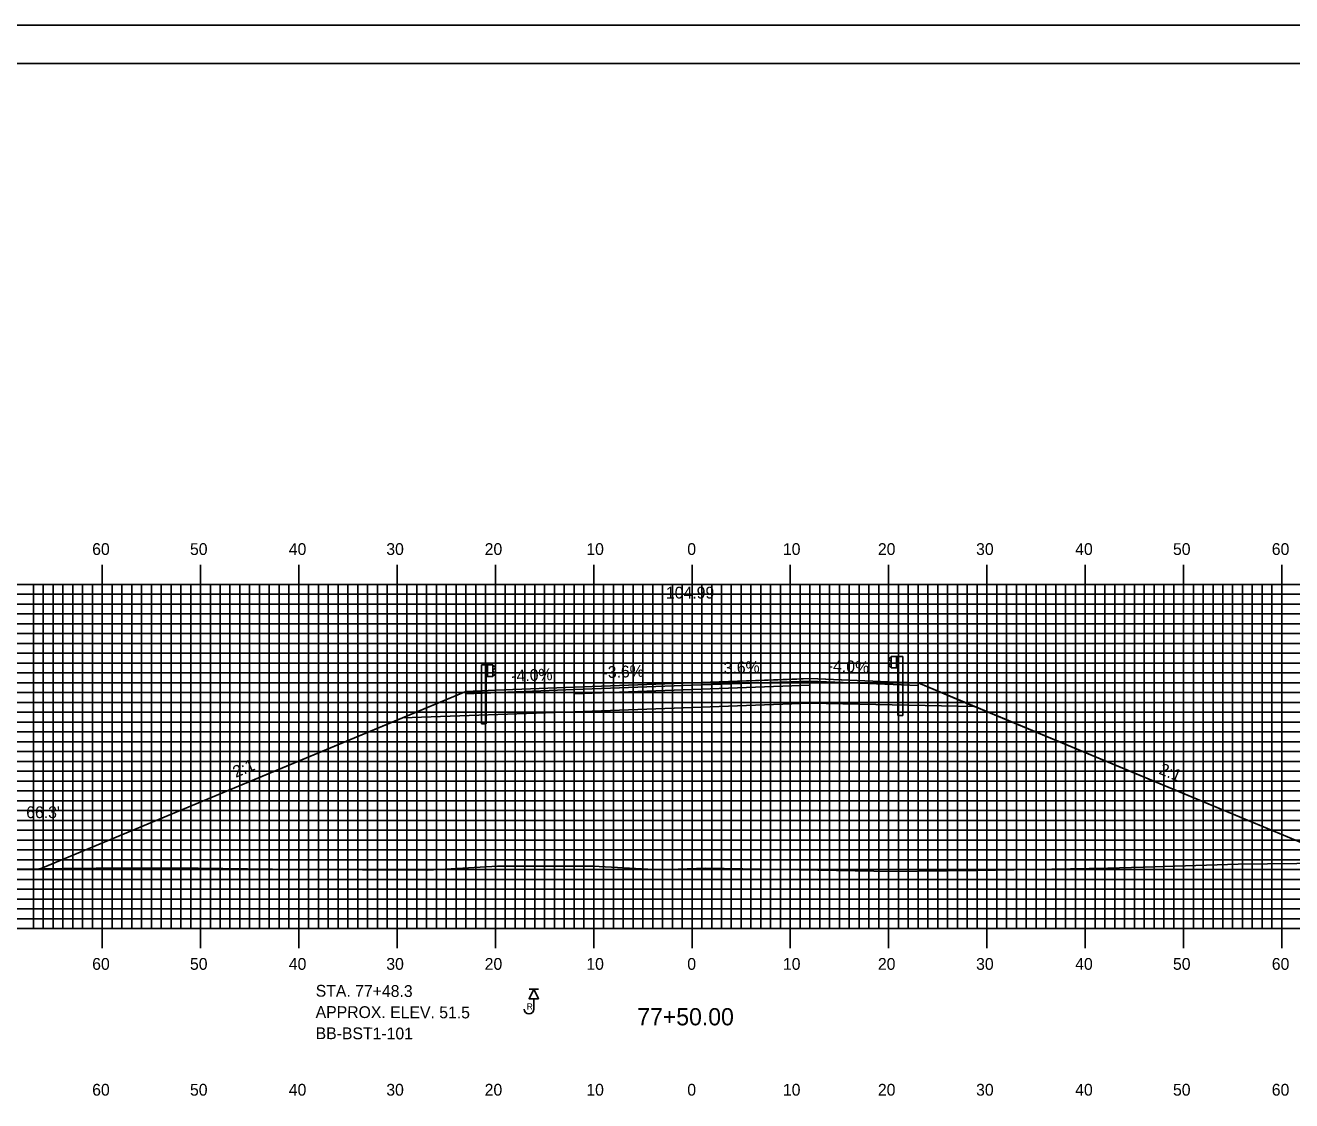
# Model space of a CAD drawing. Extents: x 1761791 to 1762134, y 442591 to 442811.
# Drawn here: x 1761888.9 to 1762017.8, y 442701.2 to 442810.5 of the extents above; entities that cross this region are included whole.
import ezdxf

# ---------------------------------------------------------------- set-up
doc = ezdxf.new("R2010")
doc.units = 0
for name, color, linetype in [('ANNOTATION', 7, 'Continuous'), ('BORDER', 7, 'Continuous'), ('BORING - REFUSAL', 7, 'Continuous'), ('D_Guardrail_Beam_Lt', 7, 'Continuous'), ('D_Guardrail_Beam_Rt', 7, 'Continuous'), ('D_Roadway_Centerline', 7, 'Continuous'), ('D_Roadway_Centerline_Text', 7, 'Continuous'), ('D_Roadway_Edge_Shoulder', 7, 'Continuous'), ('D_Roadway_Edge_TW', 7, 'Continuous'), ('D_Roadway_Pavement', 7, 'Continuous'), ('D_Roadway_SlopeLines', 7, 'Continuous'), ('D_Roadway_SubGrade', 7, 'Continuous'), ('D_Text_Standard', 7, 'Continuous'), ('H_V ANNOTATION', 7, 'Continuous'), ('MAJOR', 7, 'Continuous'), ('MINOR', 7, 'Continuous'), ('PLOT BOUNDARY', 7, 'Continuous'), ('S_Roadway_Centerline', 7, 'Continuous')]:
    doc.layers.add(name, color=color, linetype=linetype)

msp = doc.modelspace()

# ---------------------------------------------------------------- linework, layer by layer
at = {"layer": 'BORDER'}
msp.add_lwpolyline([(1761807.15, 442596.67), (1762127.15, 442596.67), (1762127.15, 442806.67), (1761807.15, 442806.67)], close=True, dxfattribs=at)
at = {"layer": 'BORING - REFUSAL'}
for p, q in [((1761941.13, 442712.49), (1761940.17, 442712.49)), ((1761940.65, 442711.53), (1761940.65, 442710.47))]:
    msp.add_line(p, q, dxfattribs=at)
msp.add_lwpolyline([(1761940.65, 442712.49), (1761941.13, 442711.53), (1761940.17, 442711.53)], close=True, dxfattribs=at)
msp.add_arc((1761940.17, 442710.47), 0.485, 180, 0, dxfattribs=at)
at = {"layer": 'D_Guardrail_Beam_Lt'}
for p, q in [((1761935.32, 442745.49), (1761935.32, 442739.49)), ((1761935.79, 442745.49), (1761935.32, 442745.49)), ((1761936.48, 442745.49), (1761935.79, 442745.49)), ((1761935.79, 442745.49), (1761935.79, 442744.32)), ((1761935.86, 442745.49), (1761935.86, 442744.32)), ((1761935.96, 442745.49), (1761935.96, 442744.32)), ((1761936.48, 442744.32), (1761936.48, 442745.49)), ((1761936.48, 442745.4), (1761936.56, 442745.39)), ((1761936.49, 442744.94), (1761936.49, 442744.87)), ((1761936.72, 442745.14), (1761936.52, 442745)), ((1761936.52, 442744.8), (1761936.72, 442744.67)), ((1761936.57, 442745.38), (1761936.72, 442745.28)), ((1761936.72, 442744.52), (1761936.57, 442744.42)), ((1761935.79, 442744.32), (1761936.48, 442744.32)), ((1761935.82, 442739.49), (1761935.82, 442744.32)), ((1761936.56, 442744.42), (1761936.48, 442744.4)), ((1761935.82, 442739.49), (1761935.32, 442739.49))]:
    msp.add_line(p, q, dxfattribs=at)
for centre, major_axis, start_param, end_param in [((1761936.57, 442744.94), (-0.0789, 0), 5.323254, 6.283185), ((1761936.57, 442744.87), (-0.0789, 0), 6.283185, 7.243116), ((1761936.55, 442745.35), (0.0417, 0), 0.959931, 1.376053), ((1761936.55, 442744.46), (0.0417, 0), 4.907132, 5.323254), ((1761936.67, 442745.21), (0.0877, 0), 5.323254, 7.243116), ((1761936.67, 442744.6), (0.0877, 0), 5.323254, 7.243116)]:
    msp.add_ellipse(centre, major_axis=major_axis, ratio=0.995501, start_param=start_param, end_param=end_param, dxfattribs=at)
at = {"layer": 'D_Guardrail_Beam_Rt'}
for p, q in [((1761976.93, 442746.25), (1761976.79, 442746.15)), ((1761976.79, 442746), (1761976.99, 442745.87)), ((1761977.02, 442746.27), (1761976.95, 442746.25)), ((1761977.02, 442746.35), (1761977.71, 442746.35)), ((1761977.02, 442745.18), (1761977.02, 442746.35)), ((1761977.02, 442745.8), (1761977.02, 442745.73)), ((1761977.55, 442746.35), (1761977.55, 442745.18)), ((1761977.65, 442746.35), (1761977.65, 442745.18)), ((1761977.71, 442746.35), (1761978.18, 442746.35)), ((1761977.71, 442746.35), (1761977.71, 442745.18)), ((1761978.18, 442746.35), (1761978.18, 442740.35)), ((1761976.99, 442745.67), (1761976.79, 442745.53)), ((1761976.79, 442745.39), (1761976.93, 442745.29)), ((1761976.95, 442745.28), (1761977.02, 442745.27)), ((1761977.71, 442745.18), (1761977.02, 442745.18)), ((1761977.69, 442740.35), (1761977.69, 442745.18)), ((1761977.69, 442740.35), (1761978.18, 442740.35))]:
    msp.add_line(p, q, dxfattribs=at)
for centre, major_axis, start_param, end_param in [((1761976.84, 442746.07), (-0.0877, 0), 5.323254, 7.243116), ((1761976.96, 442746.21), (-0.0417, 0), 4.907132, 5.323254), ((1761976.94, 442745.8), (0.0789, 0), 0, 0.959931), ((1761976.94, 442745.73), (0.0789, 0), 5.323254, 6.283185), ((1761976.84, 442745.46), (-0.0877, 0), 5.323254, 7.243116), ((1761976.96, 442745.32), (-0.0417, 0), 0.959931, 1.376053)]:
    msp.add_ellipse(centre, major_axis=major_axis, ratio=0.995501, start_param=start_param, end_param=end_param, dxfattribs=at)
at = {"layer": 'D_Roadway_Centerline'}
msp.add_lwpolyline([(1761890.44, 442724.74), (1761927.3, 442740.09), (1761933.75, 442742.78), (1761936.75, 442742.9), (1761936.75, 442742.9), (1761944.75, 442743.22), (1761956.75, 442743.66), (1761967.41, 442744.04), (1761968.75, 442744.09), (1761968.76, 442744.09), (1761976.75, 442743.77), (1761976.76, 442743.77), (1761979.75, 442743.65), (1761985.46, 442741.27), (1761985.5, 442741.25), (1762023.27, 442725.52), (1762023.67, 442725.35)], dxfattribs=at)
at = {"layer": 'D_Roadway_Edge_Shoulder'}
for points in [[(1761944.75, 442743.22), (1761936.75, 442742.9), (1761936.75, 442742.9), (1761933.75, 442742.78), (1761933.75, 442742.53), (1761944.75, 442742.97)], [(1761968.75, 442744.09), (1761976.75, 442743.77), (1761976.75, 442743.77), (1761979.75, 442743.65), (1761979.75, 442743.4), (1761968.75, 442743.84)]]:
    msp.add_lwpolyline(points, close=True, dxfattribs=at)
at = {"layer": 'D_Roadway_Edge_TW'}
msp.add_lwpolyline([(1761944.75, 442742.97), (1761944.75, 442743.22), (1761956.75, 442743.66), (1761968.75, 442744.09), (1761968.75, 442743.84), (1761956.75, 442743.41)], close=True, dxfattribs=at)
at = {"layer": 'D_Roadway_Pavement'}
msp.add_lwpolyline([(1761944.75, 442742.56), (1761944.75, 442742.97), (1761956.75, 442743.41), (1761968.75, 442743.84), (1761968.75, 442743.42), (1761956.75, 442742.99)], close=True, dxfattribs=at)
for points in [[(1761968.75, 442743.84), (1761968.75, 442743.42)], [(1761944.75, 442742.97), (1761944.75, 442742.56)]]:
    msp.add_lwpolyline(points, dxfattribs=at)
at = {"layer": 'D_Roadway_SlopeLines'}
for points in [[(1761979.75, 442743.65), (1762023.67, 442725.35)], [(1761933.75, 442742.78), (1761890.44, 442724.74)]]:
    msp.add_lwpolyline(points, dxfattribs=at)
at = {"layer": 'D_Roadway_SubGrade'}
for points in [[(1761944.75, 442740.72), (1761944.75, 442742.97), (1761944.75, 442742.56), (1761956.75, 442742.99), (1761968.75, 442743.42), (1761968.75, 442743.84), (1761968.75, 442741.59), (1761956.75, 442741.16)], [(1761968.75, 442743.42), (1761968.75, 442743.84), (1761979.75, 442743.4), (1761979.75, 442743.65), (1761985.5, 442741.25), (1761968.75, 442741.59)], [(1761944.75, 442742.56), (1761944.75, 442742.97), (1761933.75, 442742.53), (1761933.75, 442742.78), (1761927.3, 442740.09), (1761944.75, 442740.72)]]:
    msp.add_lwpolyline(points, close=True, dxfattribs=at)
at = {"layer": 'MAJOR'}
for p, q in [((1761896.75, 442755.67), (1761896.75, 442753.67)), ((1761906.75, 442755.67), (1761906.75, 442753.67)), ((1761916.75, 442755.67), (1761916.75, 442753.67)), ((1761926.75, 442755.67), (1761926.75, 442753.67)), ((1761936.75, 442755.67), (1761936.75, 442753.67)), ((1761946.75, 442755.67), (1761946.75, 442753.67)), ((1761956.75, 442755.67), (1761956.75, 442753.67)), ((1761966.75, 442755.67), (1761966.75, 442753.67)), ((1761976.75, 442755.67), (1761976.75, 442753.67)), ((1761986.75, 442755.67), (1761986.75, 442753.67)), ((1761996.75, 442755.67), (1761996.75, 442753.67)), ((1762006.75, 442755.67), (1762006.75, 442753.67)), ((1762016.75, 442755.67), (1762016.75, 442753.67)), ((1761816.75, 442753.67), (1762096.75, 442753.67)), ((1761816.75, 442753.67), (1762096.75, 442753.67)), ((1761896.75, 442718.67), (1761896.75, 442753.67)), ((1761906.75, 442718.67), (1761906.75, 442753.67)), ((1761916.75, 442718.67), (1761916.75, 442753.67)), ((1761926.75, 442718.67), (1761926.75, 442753.67)), ((1761936.75, 442718.67), (1761936.75, 442753.67)), ((1761946.75, 442718.67), (1761946.75, 442753.67)), ((1761956.75, 442718.67), (1761956.75, 442753.67)), ((1761966.75, 442718.67), (1761966.75, 442753.67)), ((1761976.75, 442718.67), (1761976.75, 442753.67)), ((1761986.75, 442718.67), (1761986.75, 442753.67)), ((1761996.75, 442718.67), (1761996.75, 442753.67)), ((1762006.75, 442718.67), (1762006.75, 442753.67)), ((1762016.75, 442718.67), (1762016.75, 442753.67)), ((1761816.75, 442748.67), (1762096.75, 442748.67)), ((1761816.75, 442743.67), (1762096.75, 442743.67)), ((1761816.75, 442738.67), (1762096.75, 442738.67)), ((1761816.75, 442733.67), (1762096.75, 442733.67)), ((1761816.75, 442728.67), (1762096.75, 442728.67)), ((1761816.75, 442723.67), (1762096.75, 442723.67)), ((1761816.75, 442718.67), (1762096.75, 442718.67)), ((1761816.75, 442718.67), (1762096.75, 442718.67)), ((1761896.75, 442716.66), (1761896.75, 442718.67)), ((1761906.75, 442716.66), (1761906.75, 442718.67)), ((1761916.75, 442716.66), (1761916.75, 442718.67)), ((1761926.75, 442716.66), (1761926.75, 442718.67)), ((1761936.75, 442716.66), (1761936.75, 442718.67)), ((1761946.75, 442716.66), (1761946.75, 442718.67)), ((1761956.75, 442716.66), (1761956.75, 442718.67)), ((1761966.75, 442716.66), (1761966.75, 442718.67)), ((1761976.75, 442716.66), (1761976.75, 442718.67)), ((1761986.75, 442716.66), (1761986.75, 442718.67)), ((1761996.75, 442716.66), (1761996.75, 442718.67)), ((1762006.75, 442716.66), (1762006.75, 442718.67)), ((1762016.75, 442716.66), (1762016.75, 442718.67))]:
    msp.add_line(p, q, dxfattribs=at)
at = {"layer": 'MINOR'}
for p, q in [((1761889.75, 442718.67), (1761889.75, 442753.67)), ((1761890.75, 442718.67), (1761890.75, 442753.67)), ((1761891.75, 442718.67), (1761891.75, 442753.67)), ((1761892.75, 442718.67), (1761892.75, 442753.67)), ((1761893.75, 442718.67), (1761893.75, 442753.67)), ((1761894.75, 442718.67), (1761894.75, 442753.67)), ((1761895.75, 442718.67), (1761895.75, 442753.67)), ((1761897.75, 442718.67), (1761897.75, 442753.67)), ((1761898.75, 442718.67), (1761898.75, 442753.67)), ((1761899.75, 442718.67), (1761899.75, 442753.67)), ((1761900.75, 442718.67), (1761900.75, 442753.67)), ((1761901.75, 442718.67), (1761901.75, 442753.67)), ((1761902.75, 442718.67), (1761902.75, 442753.67)), ((1761903.75, 442718.67), (1761903.75, 442753.67)), ((1761904.75, 442718.67), (1761904.75, 442753.67)), ((1761905.75, 442718.67), (1761905.75, 442753.67)), ((1761907.75, 442718.67), (1761907.75, 442753.67)), ((1761908.75, 442718.67), (1761908.75, 442753.67)), ((1761909.75, 442718.67), (1761909.75, 442753.67)), ((1761910.75, 442718.67), (1761910.75, 442753.67)), ((1761911.75, 442718.67), (1761911.75, 442753.67)), ((1761912.75, 442718.67), (1761912.75, 442753.67)), ((1761913.75, 442718.67), (1761913.75, 442753.67)), ((1761914.75, 442718.67), (1761914.75, 442753.67)), ((1761915.75, 442718.67), (1761915.75, 442753.67)), ((1761917.75, 442718.67), (1761917.75, 442753.67)), ((1761918.75, 442718.67), (1761918.75, 442753.67)), ((1761919.75, 442718.67), (1761919.75, 442753.67)), ((1761920.75, 442718.67), (1761920.75, 442753.67)), ((1761921.75, 442718.67), (1761921.75, 442753.67)), ((1761922.75, 442718.67), (1761922.75, 442753.67)), ((1761923.75, 442718.67), (1761923.75, 442753.67)), ((1761924.75, 442718.67), (1761924.75, 442753.67)), ((1761925.75, 442718.67), (1761925.75, 442753.67)), ((1761927.75, 442718.67), (1761927.75, 442753.67)), ((1761928.75, 442718.67), (1761928.75, 442753.67)), ((1761929.75, 442718.67), (1761929.75, 442753.67)), ((1761930.75, 442718.67), (1761930.75, 442753.67)), ((1761931.75, 442718.67), (1761931.75, 442753.67)), ((1761932.75, 442718.67), (1761932.75, 442753.67)), ((1761933.75, 442718.67), (1761933.75, 442753.67)), ((1761934.75, 442718.67), (1761934.75, 442753.67)), ((1761935.75, 442718.67), (1761935.75, 442753.67)), ((1761937.75, 442718.67), (1761937.75, 442753.67)), ((1761938.75, 442718.67), (1761938.75, 442753.67)), ((1761939.75, 442718.67), (1761939.75, 442753.67)), ((1761940.75, 442718.67), (1761940.75, 442753.67)), ((1761941.75, 442718.67), (1761941.75, 442753.67)), ((1761942.75, 442718.67), (1761942.75, 442753.67)), ((1761943.75, 442718.67), (1761943.75, 442753.67)), ((1761944.75, 442718.67), (1761944.75, 442753.67)), ((1761945.75, 442718.67), (1761945.75, 442753.67)), ((1761947.75, 442718.67), (1761947.75, 442753.67)), ((1761948.75, 442718.67), (1761948.75, 442753.67)), ((1761949.75, 442718.67), (1761949.75, 442753.67)), ((1761950.75, 442718.67), (1761950.75, 442753.67)), ((1761951.75, 442718.67), (1761951.75, 442753.67)), ((1761952.75, 442718.67), (1761952.75, 442753.67)), ((1761953.75, 442718.67), (1761953.75, 442753.67)), ((1761954.75, 442718.67), (1761954.75, 442753.67)), ((1761955.75, 442718.67), (1761955.75, 442753.67)), ((1761957.75, 442718.67), (1761957.75, 442753.67)), ((1761958.75, 442718.67), (1761958.75, 442753.67)), ((1761959.75, 442718.67), (1761959.75, 442753.67)), ((1761960.75, 442718.67), (1761960.75, 442753.67)), ((1761961.75, 442718.67), (1761961.75, 442753.67)), ((1761962.75, 442718.67), (1761962.75, 442753.67)), ((1761963.75, 442718.67), (1761963.75, 442753.67)), ((1761964.75, 442718.67), (1761964.75, 442753.67)), ((1761965.75, 442718.67), (1761965.75, 442753.67)), ((1761967.75, 442718.67), (1761967.75, 442753.67)), ((1761968.75, 442718.67), (1761968.75, 442753.67)), ((1761969.75, 442718.67), (1761969.75, 442753.67)), ((1761970.75, 442718.67), (1761970.75, 442753.67)), ((1761971.75, 442718.67), (1761971.75, 442753.67)), ((1761972.75, 442718.67), (1761972.75, 442753.67)), ((1761973.75, 442718.67), (1761973.75, 442753.67)), ((1761974.75, 442718.67), (1761974.75, 442753.67)), ((1761975.75, 442718.67), (1761975.75, 442753.67)), ((1761977.75, 442718.67), (1761977.75, 442753.67)), ((1761978.75, 442718.67), (1761978.75, 442753.67)), ((1761979.75, 442718.67), (1761979.75, 442753.67)), ((1761980.75, 442718.67), (1761980.75, 442753.67)), ((1761981.75, 442718.67), (1761981.75, 442753.67)), ((1761982.75, 442718.67), (1761982.75, 442753.67)), ((1761983.75, 442718.67), (1761983.75, 442753.67)), ((1761984.75, 442718.67), (1761984.75, 442753.67)), ((1761985.75, 442718.67), (1761985.75, 442753.67)), ((1761987.75, 442718.67), (1761987.75, 442753.67)), ((1761988.75, 442718.67), (1761988.75, 442753.67)), ((1761989.75, 442718.67), (1761989.75, 442753.67)), ((1761990.75, 442718.67), (1761990.75, 442753.67)), ((1761991.75, 442718.67), (1761991.75, 442753.67)), ((1761992.75, 442718.67), (1761992.75, 442753.67)), ((1761993.75, 442718.67), (1761993.75, 442753.67)), ((1761994.75, 442718.67), (1761994.75, 442753.67)), ((1761995.75, 442718.67), (1761995.75, 442753.67)), ((1761997.75, 442718.67), (1761997.75, 442753.67)), ((1761998.75, 442718.67), (1761998.75, 442753.67)), ((1761999.75, 442718.67), (1761999.75, 442753.67)), ((1762000.75, 442718.67), (1762000.75, 442753.67)), ((1762001.75, 442718.67), (1762001.75, 442753.67)), ((1762002.75, 442718.67), (1762002.75, 442753.67)), ((1762003.75, 442718.67), (1762003.75, 442753.67)), ((1762004.75, 442718.67), (1762004.75, 442753.67)), ((1762005.75, 442718.67), (1762005.75, 442753.67)), ((1762007.75, 442718.67), (1762007.75, 442753.67)), ((1762008.75, 442718.67), (1762008.75, 442753.67)), ((1762009.75, 442718.67), (1762009.75, 442753.67)), ((1762010.75, 442718.67), (1762010.75, 442753.67)), ((1762011.75, 442718.67), (1762011.75, 442753.67)), ((1762012.75, 442718.67), (1762012.75, 442753.67)), ((1762013.75, 442718.67), (1762013.75, 442753.67)), ((1762014.75, 442718.67), (1762014.75, 442753.67)), ((1762015.75, 442718.67), (1762015.75, 442753.67)), ((1761816.75, 442752.67), (1762096.75, 442752.67)), ((1761816.75, 442751.67), (1762096.75, 442751.67)), ((1761816.75, 442750.67), (1762096.75, 442750.67)), ((1761816.75, 442749.67), (1762096.75, 442749.67)), ((1761816.75, 442747.67), (1762096.75, 442747.67)), ((1761816.75, 442746.67), (1762096.75, 442746.67)), ((1761816.75, 442745.67), (1762096.75, 442745.67)), ((1761816.75, 442744.67), (1762096.75, 442744.67)), ((1761816.75, 442742.67), (1762096.75, 442742.67)), ((1761816.75, 442741.67), (1762096.75, 442741.67)), ((1761816.75, 442740.67), (1762096.75, 442740.67)), ((1761816.75, 442739.67), (1762096.75, 442739.67)), ((1761816.75, 442737.67), (1762096.75, 442737.67)), ((1761816.75, 442736.67), (1762096.75, 442736.67)), ((1761816.75, 442735.67), (1762096.75, 442735.67)), ((1761816.75, 442734.67), (1762096.75, 442734.67)), ((1761816.75, 442732.67), (1762096.75, 442732.67)), ((1761816.75, 442731.67), (1762096.75, 442731.67)), ((1761816.75, 442730.67), (1762096.75, 442730.67)), ((1761816.75, 442729.67), (1762096.75, 442729.67)), ((1761816.75, 442727.67), (1762096.75, 442727.67)), ((1761816.75, 442726.67), (1762096.75, 442726.67)), ((1761816.75, 442725.67), (1762096.75, 442725.67)), ((1761816.75, 442724.67), (1762096.75, 442724.67)), ((1761816.75, 442722.67), (1762096.75, 442722.67)), ((1761816.75, 442721.67), (1762096.75, 442721.67)), ((1761816.75, 442720.67), (1762096.75, 442720.67)), ((1761816.75, 442719.67), (1762096.75, 442719.67))]:
    msp.add_line(p, q, dxfattribs=at)
at = {"layer": 'PLOT BOUNDARY'}
msp.add_lwpolyline([(1761790.97, 442590.55), (1762130.97, 442590.55), (1762130.97, 442810.55), (1761790.97, 442810.55)], close=True, dxfattribs=at)
at = {"layer": 'S_Roadway_Centerline'}
msp.add_lwpolyline([(1761882.62, 442724.64), (1761892.85, 442724.76), (1761894.95, 442724.78), (1761896.14, 442724.81), (1761906.51, 442724.8), (1761916.59, 442724.66), (1761929.88, 442724.61), (1761936.96, 442725.01), (1761946.71, 442725.01), (1761953.48, 442724.65), (1761958.12, 442724.8), (1761975.24, 442724.5), (1761976.67, 442724.47), (1761985.72, 442724.58), (1761999.06, 442724.8), (1762002.65, 442724.92), (1762012.3, 442725.23), (1762030.19, 442725.42)], dxfattribs=at)

# ---------------------------------------------------------------- texts
at = {"layer": 'ANNOTATION'}
for s, rotation, p in [('3.6%', 2.0618, (1761959.99, 442744.57)), ('-4.0%', 357.7095, (1761970.55, 442744.82)), ('-4.0%', 2.2905, (1761938.39, 442743.77)), ('-3.6%', 2.0618, (1761947.67, 442744.13)), ('2:1', 22.6203, (1761910.34, 442733.99)), ('2:1', 337.3804, (1762004.16, 442734.44))]:
    msp.add_text(s, height=1.2, rotation=rotation, dxfattribs=at).set_placement(p)
at = {"layer": 'BORING - REFUSAL'}
for s, p in [('STA. 77+48.3', (1761918.47, 442711.74)), ('APPROX. ELEV. 51.5', (1761918.46, 442709.58)), ('BB-BST1-101', (1761918.46, 442707.42))]:
    msp.add_text(s, height=1.2, rotation=359.8142, dxfattribs=at).set_placement(p)
msp.add_text('R', height=0.64, dxfattribs=at).set_placement((1761939.94, 442710.41))
at = {"layer": 'D_Roadway_Centerline'}
for s, p in [('C', (1761956.75, 442743.66)), ('L', (1761956.75, 442743.65))]:
    msp.add_text(s, height=0.0146, dxfattribs=at).set_placement(p)
at = {"layer": 'D_Roadway_Centerline_Text'}
msp.add_text('104.99', height=1.2, dxfattribs=at).set_placement((1761954.1, 442752.24))
at = {"layer": 'D_Text_Standard'}
msp.add_text("66.3'", height=1.2, dxfattribs=at).set_placement((1761889.02, 442729.9))
at = {"layer": 'H_V ANNOTATION'}
for s, height, p in [('60', 1.2, (1761895.73, 442756.67)), ('50', 1.2, (1761905.68, 442756.67)), ('40', 1.2, (1761915.73, 442756.67)), ('30', 1.2, (1761925.65, 442756.67)), ('20', 1.2, (1761935.66, 442756.67)), ('10', 1.2, (1761946, 442756.67)), ('0', 1.2, (1761956.27, 442756.67)), ('10', 1.2, (1761966, 442756.67)), ('20', 1.2, (1761975.66, 442756.67)), ('30', 1.2, (1761985.65, 442756.67)), ('40', 1.2, (1761995.73, 442756.67)), ('50', 1.2, (1762005.68, 442756.67)), ('60', 1.2, (1762015.73, 442756.67)), ('60', 1.2, (1761895.73, 442714.47)), ('50', 1.2, (1761905.68, 442714.47)), ('40', 1.2, (1761915.73, 442714.47)), ('30', 1.2, (1761925.65, 442714.47)), ('20', 1.2, (1761935.66, 442714.47)), ('10', 1.2, (1761946, 442714.47)), ('0', 1.2, (1761956.27, 442714.47)), ('10', 1.2, (1761966, 442714.47)), ('20', 1.2, (1761975.66, 442714.47)), ('30', 1.2, (1761985.65, 442714.47)), ('40', 1.2, (1761995.73, 442714.47)), ('50', 1.2, (1762005.68, 442714.47)), ('60', 1.2, (1762015.73, 442714.47)), ('77+50.00', 1.75, (1761951.18, 442708.82)), ('60', 1.2, (1761895.73, 442701.67)), ('50', 1.2, (1761905.68, 442701.67)), ('40', 1.2, (1761915.73, 442701.67)), ('30', 1.2, (1761925.65, 442701.67)), ('20', 1.2, (1761935.66, 442701.67)), ('10', 1.2, (1761946, 442701.67)), ('0', 1.2, (1761956.27, 442701.67)), ('10', 1.2, (1761966, 442701.67)), ('20', 1.2, (1761975.66, 442701.67)), ('30', 1.2, (1761985.65, 442701.67)), ('40', 1.2, (1761995.73, 442701.67)), ('50', 1.2, (1762005.68, 442701.67)), ('60', 1.2, (1762015.73, 442701.67))]:
    msp.add_text(s, height=height, dxfattribs=at).set_placement(p)

doc.saveas('drawing.dxf')
